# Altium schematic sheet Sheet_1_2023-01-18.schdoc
size 227 x 132 mm
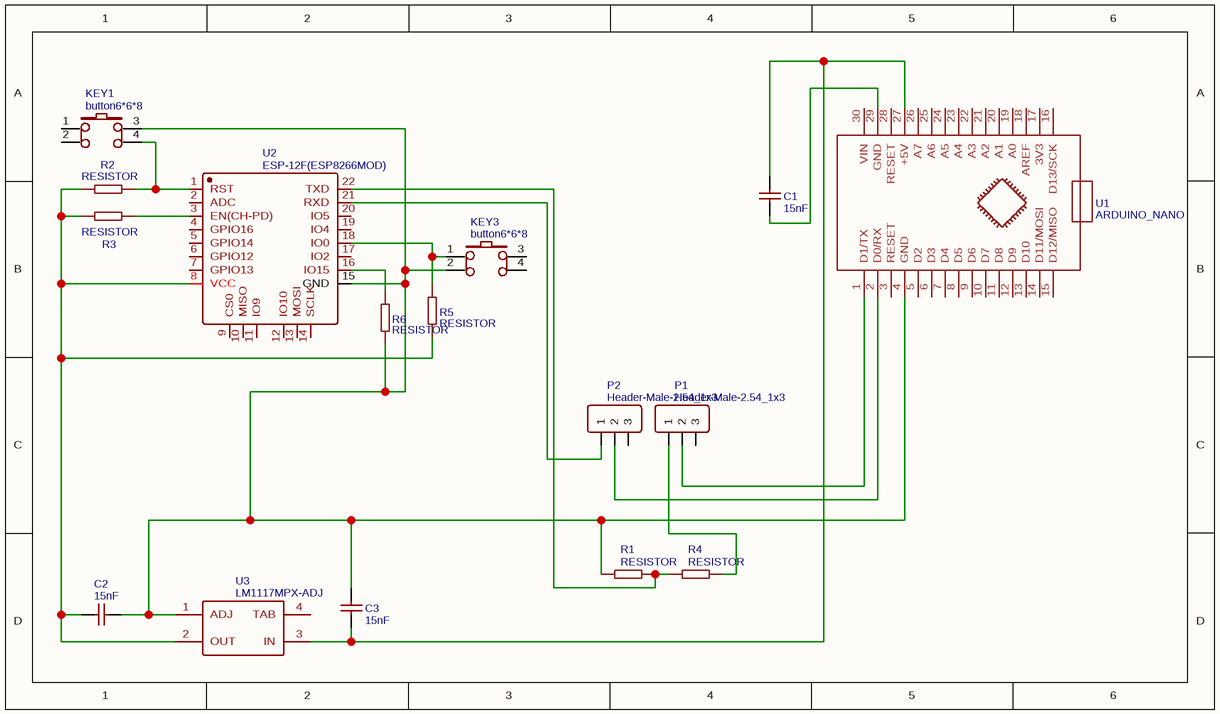
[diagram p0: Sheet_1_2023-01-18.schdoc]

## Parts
C1  15nF  [CAP-CBB-6.5*4.0]
C2  15nF  [CAP-CBB-6.5*4.0]
C3  15nF  [CAP-CBB-6.5*4.0]
KEY1  button6*6*8  [KEY-6.0*6.0-2]
KEY3  button6*6*8  [KEY-6.0*6.0-2]
P1  Header-Male-2.54_1x3  [HDR-3X1/2.54]
P2  Header-Male-2.54_1x3  [HDR-3X1/2.54]
R1  RESISTOR  [RTH025W]
R2  RESISTOR  [RTH025W]
R3  RESISTOR  [RTH025W]
R4  RESISTOR  [RTH025W]
R5  RESISTOR  [RTH025W]
R6  RESISTOR  [RTH025W]
U1  ARDUINO_NANO  [ARDUINO_NANO]
U2  ESP-12F(ESP8266MOD)  [ESP-12F(ESP8266MOD)]
U3  LM1117MPX-ADJ  [SOT-223]

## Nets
NetC1_1: C1.1 U1.29(GND)
NetC1_2: C1.2 C3.1 U1.27(+5V) U3.3(IN)
NetC2_1: C2.1 C3.2 KEY1.3 KEY3.2 R1.1 R6.2 U1.4(GND) U2.15(GND) U3.1(ADJ)
NetC2_2: C2.2 R2.2 R3.2 R5.2 U2.8(VCC) U3.2(OUT)
NetKEY1_4: KEY1.4 R2.1 U2.1(RST)
NetKEY3_1: KEY3.1 R5.1 U2.18(IO0)
NetP1_1: P1.1 R4.2
NetP1_2: P1.2 U1.1(D1/TX)
NetP2_1: P2.1 U2.21(RXD)
NetP2_2: P2.2 U1.2(D0/RX)
NetR1_2: R1.2 R4.1 U2.22(TXD)
NetR3_1: R3.1 U2.3(EN(CH-PD))
NetR6_1: R6.1 U2.16(IO15)

Not connected (* = marked no-connect by the designer): KEY1 1 2; KEY3 3 4; P1 3; P2 3; U1 3(RESET) 5(D2) 6(D3) 7(D4) 8(D5) 9(D6) 10(D7) 11(D8) 12(D9) 13(D10) 14(D11/MOSI) 15(D12/MISO) 16(D13/SCK) 17(3V3) 18(AREF) 19(A0) 20(A1) 21(A2) 22(A3) 23(A4) 24(A5) 25(A6) 26(A7) 28(RESET) 30(VIN); U2 2(ADC) 4(GPIO16) 5(GPIO14) 6(GPIO12) 7(GPIO13) 9(CS0) 10(MISO) 11(IO9) 12(IO10) 13(MOSI) 14(SCLK) 17(IO2) 19(IO4) 20(IO5); U3 4(TAB)

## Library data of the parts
C1-C3 = 15nF: BOM_Manufacturer: ReliaPro; BOM_Manufacturer Part: Capacitor15nf100v; nameAlias: Capacitance; Contributor: LCSC
KEY1 KEY3 = button6*6*8: BOM_Manufacturer: ReliaPro
P1 P2 = Header-Male-2.54_1x3: BOM_Manufacturer: BOOMELE; BOM_Manufacturer Part: Header2.54mm 1*3P
R1-R6 = RESISTOR: Contributor: DangerousPrototype
U1 = ARDUINO_NANO: sourceId: KGSeAWhDB
U2 = ESP-12F(ESP8266MOD): BOM_Manufacturer: Ai-Thinker
U3 = LM1117MPX-ADJ: BOM_Manufacturer: TI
